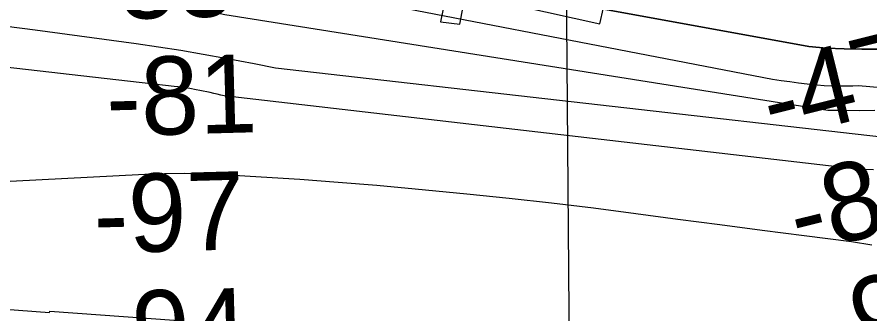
# Model space of a CAD drawing. Extents: x 3445503 to 3483459, y 540493 to 566012.
# Drawn here: x 3471584 to 3472315, y 551564 to 551818 of the extents above; entities that cross this region are included whole.
import ezdxf

# ---------------------------------------------------------------- set-up
doc = ezdxf.new("R2010")
doc.units = 0
for name, color, linetype in [('V-CHAN-DOCK', 7, 'Continuous'), ('V-RIVR-RANG', 7, 'Continuous'), ('V-RRAP-RVMT', 7, 'Continuous'), ('V-TOPO-DPTH', 7, 'Continuous'), ('V-TOPO-MAJR', 7, 'Continuous'), ('V-TOPO-MINR', 7, 'Continuous'), ('V-UTIL-LINE', 7, 'Continuous')]:
    doc.layers.add(name, color=color, linetype=linetype)

msp = doc.modelspace()

# ---------------------------------------------------------------- linework, layer by layer
at = {"layer": 'V-CHAN-DOCK'}
msp.add_lwpolyline([(3472086.9, 551825.95), (3471851.21, 551878.73), (3471848.15, 551865.07), (3471871.19, 551859.91), (3471864.62, 551830.58), (3471881.25, 551827.95), (3471884.03, 551841.47), (3471949.35, 551825.16), (3471947.1, 551813.94), (3471963.72, 551812), (3471968.59, 551838.09), (3472083.84, 551812.28), (3472086.9, 551825.95)], dxfattribs=at)
at = {"layer": 'V-RRAP-RVMT'}
msp.add_lwpolyline([(3470688.68, 551820.3), (3470671.97, 551665.91), (3470796.2, 551654.1), (3470798.62, 551671.65), (3471035.94, 551647.49), (3471035.39, 551641.89), (3471176.03, 551629.98), (3471174.23, 551591.14), (3471343, 551579.19), (3471344.94, 551605.47), (3471469.22, 551598.51), (3471467.22, 551575.83), (3471611.76, 551564.94), (3471612.01, 551566.08), (3471718.62, 551558.47), (3471720.38, 551533.09), (3471860.68, 551525.43), (3471860.38, 551512.45), (3472011.46, 551506.77), (3472012.09, 551513.12), (3472147.99, 551497.98), (3472151, 551520.1)], dxfattribs=at)
at = {"layer": 'V-TOPO-DPTH'}
for points in [[(3472323.51, 551790.61), (3472308.36, 551790.5), (3472293.24, 551790.77), (3472278.13, 551791.59), (3472263.04, 551792.8), (3471813.53, 551874.98), (3471798.34, 551878.02), (3471762.06, 551884.58), (3471742.04, 551888.04), (3471722, 551891.28), (3471701.9, 551894.22), (3471681.77, 551896.94), (3471598.22, 551907.57), (3471536.38, 551915.98)], [(3471536.38, 551915.98), (3471598.22, 551907.57), (3471681.77, 551896.94), (3471701.9, 551894.22), (3471722, 551891.28), (3471742.04, 551888.04), (3471762.06, 551884.58), (3471798.34, 551878.02), (3471813.53, 551874.98), (3472263.04, 551792.8), (3472278.13, 551791.59), (3472293.24, 551790.77), (3472308.36, 551790.5), (3472323.51, 551790.61)]]:
    msp.add_lwpolyline(points, dxfattribs=at)
at = {"layer": 'V-TOPO-MAJR'}
msp.add_lwpolyline([(3472781.27, 551717.28), (3472305.6, 551759.12), (3472300.81, 551758.94), (3472298.42, 551758.9), (3472296.02, 551758.89), (3472288.52, 551758.9), (3472282.39, 551759.02), (3472276.25, 551759.28), (3472270.14, 551759.75), (3472264.03, 551760.36), (3472261.43, 551760.66), (3472254.03, 551761.56), (3472246.63, 551762.5), (3472239.25, 551763.52), (3472231.87, 551764.57), (3471793.59, 551849.41)], dxfattribs=at)
at = {"layer": 'V-TOPO-MINR'}
for points in [[(3472323.51, 551790.61), (3472308.36, 551790.5), (3472293.24, 551790.77), (3472278.13, 551791.59), (3472263.04, 551792.8), (3471813.53, 551874.98), (3471798.34, 551878.02), (3471762.06, 551884.58), (3471742.04, 551888.04), (3471722, 551891.28), (3471701.9, 551894.22), (3471681.77, 551896.94), (3471598.22, 551907.57), (3471536.38, 551915.98)], [(3472319.46, 551738.02), (3472306.07, 551737.87), (3472292.68, 551737.94), (3472279.28, 551738.14), (3471762.09, 551820.03), (3471742.82, 551824.34), (3471723.52, 551828.44), (3471704.15, 551832.23), (3471684.74, 551835.79), (3471665.26, 551838.94), (3471645.73, 551841.74), (3471626.14, 551844.03), (3471606.5, 551845.96), (3471518.53, 551853.45)], [(3472338, 551713.77), (3471805.63, 551774.33), (3471787.15, 551777.95), (3471762.68, 551782.66), (3471743.61, 551786.17), (3471724.5, 551789.45), (3471705.34, 551792.41), (3471686.14, 551795.15), (3471599.33, 551806.77), (3471536.66, 551814.85)], [(3472318.53, 551687.22), (3472307.14, 551687.58), (3471761.56, 551750.64), (3471758.55, 551751.27), (3471755.55, 551751.92), (3471752.55, 551752.62), (3471749.56, 551753.34), (3471746.57, 551754.04), (3471743.57, 551754.7), (3471740.55, 551755.29), (3471737.53, 551755.84), (3471731.99, 551756.79), (3471728.68, 551757.33), (3471725.37, 551757.83), (3471722.05, 551758.27), (3471718.73, 551758.68), (3471435.83, 551790.99)], [(3472317, 551622.58), (3472299.53, 551625.42), (3472259.1, 551630.6), (3472222.94, 551635.27), (3472186.79, 551639.98), (3472150.64, 551644.75), (3472114.5, 551649.57), (3472078.34, 551654.22), (3472042.15, 551658.6), (3472005.91, 551662.6), (3471969.64, 551666.33), (3471925.42, 551670.64), (3471892.43, 551673.67), (3471859.42, 551676.44), (3471826.39, 551678.83), (3471793.33, 551680.98), (3471760.78, 551682.9), (3471743.98, 551683.61), (3471727.19, 551683.95), (3471710.39, 551683.73), (3471693.59, 551683.13), (3471396.32, 551667.64)]]:
    msp.add_lwpolyline(points, dxfattribs=at)
at = {"layer": 'V-UTIL-LINE'}
msp.add_lwpolyline([(3472075.06, 549359.46), (3472054.63, 551921.5)], dxfattribs=at)

# ---------------------------------------------------------------- texts
at = {"layer": 'V-RIVR-RANG'}
for s, rotation, p in [('-55', 1.55733, (3471641.99, 551815.48)), ('-47', 13.96028, (3472231.46, 551712.05)), ('-81', 1.55733, (3471661.07, 551715.96)), ('-86', 13.96028, (3472254.59, 551614.76)), ('-97', 1.55733, (3471650.35, 551615.63)), ('-96', 13.96028, (3472279.5, 551517.91)), ('-94', 1.55733, (3471653.36, 551515.68))]:
    msp.add_text(s, height=67, rotation=rotation, dxfattribs=at).set_placement(p)

doc.saveas('drawing.dxf')
